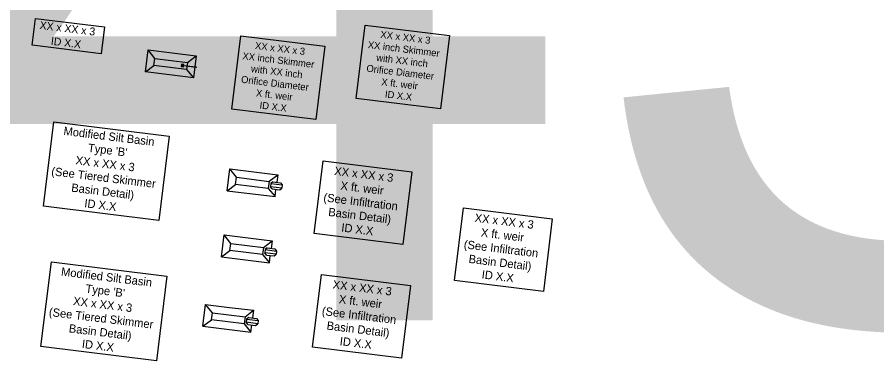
# Model space of a CAD drawing. Extents: x 2470000 to 2520000, y 340000 to 380000.
# Drawn here: x 2482787 to 2483776, y 373398 to 373794 of the extents above; entities that cross this region are included whole.
import ezdxf

# ---------------------------------------------------------------- set-up
doc = ezdxf.new("R2010")
doc.units = 0
for name, color, linetype in [('Infiltration Basin Both CELL', 7, 'Continuous'), ('Infiltration Basin CG CELL', 7, 'Continuous'), ('Infiltration Basin Final CELL', 7, 'Continuous'), ('Infiltration Basin Note Both CELL', 7, 'Continuous'), ('Infiltration Basin Note CG CELL', 7, 'Continuous'), ('Infiltration Basin Note Final CELL', 7, 'Continuous'), ('Modified Silt Basin Type B Note Both CELL', 7, 'Continuous'), ('Modified Silt Basin Type B Note Final CELL', 7, 'Continuous'), ('Scratch_Level_6', 7, 'Continuous'), ('Silt Basin Type B Note Final CELL', 7, 'Continuous'), ('Skimmer Basin Final CELL', 7, 'Continuous'), ('Skimmer Basin Note Both CELL', 7, 'Continuous'), ('Skimmer Basin Note Final CELL', 7, 'Continuous')]:
    doc.layers.add(name, color=color, linetype=linetype)

msp = doc.modelspace()

# ---------------------------------------------------------------- linework, layer by layer
at = {"layer": 'Infiltration Basin Both CELL'}
for p, q in [((2483021.8, 373517.92), (2483024.91, 373543.09)), ((2483032.65, 373533.35), (2483024.91, 373543.09)), ((2483024.91, 373543.09), (2483052.49, 373539.7)), ((2483052.49, 373539.7), (2483080.06, 373536.29)), ((2483031.66, 373525.19), (2483032.65, 373533.35)), ((2483032.65, 373533.35), (2483070.21, 373528.67)), ((2483070.23, 373528.73), (2483080.06, 373536.29)), ((2483080.06, 373536.29), (2483079, 373527.59)), ((2483021.8, 373517.92), (2483031.68, 373525.16)), ((2483069.21, 373520.54), (2483031.66, 373525.19)), ((2483070.21, 373528.67), (2483069.21, 373520.54)), ((2483069.21, 373520.54), (2483076.99, 373511.14)), ((2483072.07, 373526.15), (2483071.63, 373522.49)), ((2483073.59, 373519.98), (2483071.63, 373522.49)), ((2483084.92, 373520.87), (2483071.63, 373522.49)), ((2483074.58, 373528.12), (2483072.07, 373526.15)), ((2483072.07, 373526.15), (2483085.37, 373524.55)), ((2483073.59, 373519.98), (2483082.41, 373518.91)), ((2483074.58, 373528.12), (2483083.42, 373527.05)), ((2483082.41, 373518.91), (2483084.92, 373520.87)), ((2483083.42, 373527.05), (2483085.37, 373524.55)), ((2483085.37, 373524.55), (2483084.92, 373520.87)), ((2483021.8, 373517.92), (2483076.99, 373511.14)), ((2483076.99, 373511.14), (2483078.01, 373519.46))]:
    msp.add_line(p, q, dxfattribs=at)
at = {"layer": 'Infiltration Basin CG CELL'}
for p, q in [((2483028.31, 373594.06), (2483031.42, 373619.22)), ((2483039.16, 373609.49), (2483031.42, 373619.22)), ((2483031.42, 373619.22), (2483059, 373615.83)), ((2483038.17, 373601.33), (2483039.16, 373609.49)), ((2483039.16, 373609.49), (2483076.72, 373604.8)), ((2483059, 373615.83), (2483086.57, 373612.43)), ((2483076.74, 373604.87), (2483086.57, 373612.43)), ((2483086.57, 373612.43), (2483085.51, 373603.72)), ((2483028.31, 373594.06), (2483038.18, 373601.29)), ((2483075.72, 373596.68), (2483038.17, 373601.33)), ((2483076.72, 373604.8), (2483075.72, 373596.68)), ((2483078.58, 373602.29), (2483078.14, 373598.62)), ((2483081.09, 373604.25), (2483078.58, 373602.29)), ((2483078.58, 373602.29), (2483091.88, 373600.69)), ((2483081.09, 373604.25), (2483089.92, 373603.19)), ((2483089.92, 373603.19), (2483091.88, 373600.69)), ((2483091.88, 373600.69), (2483091.43, 373597.01)), ((2483028.31, 373594.06), (2483083.5, 373587.27)), ((2483075.72, 373596.68), (2483083.5, 373587.27)), ((2483080.1, 373596.12), (2483078.14, 373598.62)), ((2483091.43, 373597.01), (2483078.14, 373598.62)), ((2483080.1, 373596.12), (2483088.92, 373595.05)), ((2483083.5, 373587.27), (2483084.52, 373595.6)), ((2483088.92, 373595.05), (2483091.43, 373597.01))]:
    msp.add_line(p, q, dxfattribs=at)
at = {"layer": 'Infiltration Basin Final CELL'}
for p, q in [((2483000.57, 373437.9), (2483003.68, 373463.06)), ((2483011.41, 373453.33), (2483003.68, 373463.06)), ((2483003.68, 373463.06), (2483031.25, 373459.67)), ((2483010.43, 373445.17), (2483011.41, 373453.33)), ((2483011.41, 373453.33), (2483048.97, 373448.64)), ((2483031.25, 373459.67), (2483058.83, 373456.26)), ((2483049, 373448.71), (2483058.83, 373456.26)), ((2483058.83, 373456.26), (2483057.76, 373447.56)), ((2483000.57, 373437.9), (2483010.44, 373445.13)), ((2483047.97, 373440.52), (2483010.43, 373445.17)), ((2483048.97, 373448.64), (2483047.97, 373440.52)), ((2483050.83, 373446.13), (2483050.4, 373442.46)), ((2483052.35, 373439.96), (2483050.4, 373442.46)), ((2483063.68, 373440.84), (2483050.4, 373442.46)), ((2483053.35, 373448.09), (2483050.83, 373446.13)), ((2483050.83, 373446.13), (2483064.13, 373444.53)), ((2483053.35, 373448.09), (2483062.18, 373447.03)), ((2483061.17, 373438.88), (2483063.68, 373440.84)), ((2483062.18, 373447.03), (2483064.13, 373444.53)), ((2483064.13, 373444.53), (2483063.68, 373440.84)), ((2483000.57, 373437.9), (2483055.75, 373431.11)), ((2483047.97, 373440.52), (2483055.75, 373431.11)), ((2483052.35, 373439.96), (2483061.17, 373438.88)), ((2483055.75, 373431.11), (2483056.78, 373439.43))]:
    msp.add_line(p, q, dxfattribs=at)
at = {"layer": 'Infiltration Basin Note Both CELL'}
msp.add_lwpolyline([(2483137.07, 373497.55), (2483239.16, 373485), (2483228.86, 373401.19), (2483126.77, 373413.74)], close=True, dxfattribs=at)
at = {"layer": 'Infiltration Basin Note CG CELL'}
msp.add_lwpolyline([(2483138.91, 373628.4), (2483240.99, 373615.85), (2483230.69, 373532.04), (2483128.61, 373544.59)], close=True, dxfattribs=at)
at = {"layer": 'Infiltration Basin Note Final CELL'}
msp.add_lwpolyline([(2483300.39, 373574.36), (2483402.47, 373561.81), (2483392.17, 373478), (2483290.09, 373490.55)], close=True, dxfattribs=at)
at = {"layer": 'Modified Silt Basin Type B Note Both CELL'}
msp.add_lwpolyline([(2482829, 373673.38), (2482961.91, 373657.04), (2482949.96, 373559.84), (2482817.05, 373576.18)], close=True, dxfattribs=at)
at = {"layer": 'Modified Silt Basin Type B Note Final CELL'}
msp.add_lwpolyline([(2482826.25, 373511.93), (2482959.16, 373495.59), (2482947.17, 373398.08), (2482814.26, 373414.42)], close=True, dxfattribs=at)
at = {"layer": 'Silt Basin Type B Note Final CELL'}
msp.add_lwpolyline([(2482807.82, 373792.46), (2482887.42, 373782.68), (2482883.64, 373751.88), (2482804.04, 373761.66)], close=True, dxfattribs=at)
at = {"layer": 'Skimmer Basin Final CELL'}
for p, q in [((2482934.37, 373730.98), (2482937.48, 373756.15)), ((2482945.21, 373746.41), (2482937.48, 373756.15)), ((2482937.48, 373756.15), (2482965.05, 373752.76)), ((2482965.05, 373752.76), (2482992.63, 373749.35)), ((2482982.8, 373741.79), (2482992.63, 373749.35)), ((2482992.63, 373749.35), (2482989.55, 373724.2)), ((2482934.37, 373730.98), (2482944.24, 373738.22)), ((2482944.23, 373738.25), (2482945.21, 373746.41)), ((2482981.77, 373733.61), (2482944.23, 373738.25)), ((2482945.21, 373746.41), (2482982.77, 373741.73)), ((2482975.84, 373739.91), (2482975.49, 373737.07)), ((2482978.49, 373739.58), (2482975.84, 373739.91)), ((2482976.25, 373739.39), (2482976.02, 373737.47)), ((2482976.02, 373737.47), (2482977.73, 373737.26)), ((2482977.96, 373739.17), (2482976.25, 373739.39)), ((2482977.73, 373737.26), (2482977.96, 373739.17)), ((2482978.14, 373736.74), (2482978.49, 373739.58)), ((2482992.86, 373736.12), (2482978.28, 373737.93)), ((2482978.34, 373738.39), (2482992.92, 373736.58)), ((2482982.77, 373741.73), (2482981.77, 373733.61)), ((2482961.99, 373727.59), (2482934.37, 373730.98)), ((2482989.58, 373724.18), (2482961.99, 373727.59)), ((2482975.49, 373737.07), (2482978.14, 373736.74)), ((2482981.77, 373733.61), (2482989.55, 373724.2)), ((2482992.92, 373736.58), (2482992.86, 373736.12))]:
    msp.add_line(p, q, dxfattribs=at)
at = {"layer": 'Skimmer Basin Note Both CELL'}
msp.add_lwpolyline([(2483044.17, 373772.45), (2483140.71, 373760.58), (2483130.34, 373676.24), (2483033.81, 373688.11)], close=True, dxfattribs=at)
at = {"layer": 'Skimmer Basin Note Final CELL'}
msp.add_lwpolyline([(2483187.1, 373784.73), (2483284.31, 373772.78), (2483273.94, 373688.44), (2483176.74, 373700.39)], close=True, dxfattribs=at)

# ---------------------------------------------------------------- texts
at = {"layer": 'Infiltration Basin Note Both CELL'}
for s, height, p in [('XX x XX x 3', 9.5659, (2483149.43, 373481.53)), ('X ft. weir', 9.566, (2483156.56, 373464.59)), ('(See Infiltration', 9.5659, (2483136.96, 373450.94)), ('Basin Detail)', 9.5659, (2483142.49, 373434.19)), ('ID X.X', 9.566, (2483157.52, 373416.28))]:
    msp.add_text(s, height=height, rotation=352.99213, dxfattribs=at).set_placement(p)
at = {"layer": 'Infiltration Basin Note CG CELL'}
for s, height, p in [('XX x XX x 3', 9.5659, (2483151.26, 373612.38)), ('X ft. weir', 9.566, (2483158.4, 373595.44)), ('(See Infiltration', 9.5659, (2483138.8, 373581.79)), ('Basin Detail)', 9.5659, (2483144.33, 373565.04)), ('ID X.X', 9.566, (2483159.36, 373547.13))]:
    msp.add_text(s, height=height, rotation=352.99213, dxfattribs=at).set_placement(p)
at = {"layer": 'Infiltration Basin Note Final CELL'}
for s, height, p in [('XX x XX x 3', 9.5659, (2483312.74, 373558.34)), ('X ft. weir', 9.566, (2483319.88, 373541.4)), ('(See Infiltration', 9.5659, (2483300.27, 373527.74)), ('Basin Detail)', 9.5659, (2483305.81, 373511)), ('ID X.X', 9.566, (2483320.84, 373493.09))]:
    msp.add_text(s, height=height, rotation=352.99213, dxfattribs=at).set_placement(p)
at = {"layer": 'Modified Silt Basin Type B Note Both CELL'}
for s, height, p in [('Modified Silt Basin', 9.5659, (2482839.82, 373658.4)), ("Type 'B'", 9.566, (2482867.9, 373638.88)), ('XX x XX x 3', 9.5659, (2482853.7, 373624.56)), ('(See Tiered Skimmer', 9.5659, (2482825.78, 373611.93)), ('Basin Detail)', 9.5659, (2482848.71, 373593.05)), ('ID X.X', 9.566, (2482863.74, 373575.14))]:
    msp.add_text(s, height=height, rotation=352.99213, dxfattribs=at).set_placement(p)
at = {"layer": 'Modified Silt Basin Type B Note Final CELL'}
for s, height, p in [('Modified Silt Basin', 9.5659, (2482836.99, 373496.32)), ("Type 'B'", 9.566, (2482865.07, 373476.81)), ('XX x XX x 3', 9.5659, (2482850.88, 373462.49)), ('(See Tiered Skimmer', 9.5659, (2482822.96, 373449.86)), ('Basin Detail)', 9.5659, (2482845.89, 373430.98)), ('ID X.X', 9.566, (2482860.91, 373413.07))]:
    msp.add_text(s, height=height, rotation=352.99213, dxfattribs=at).set_placement(p)
at = {"layer": 'Scratch_Level_6'}
msp.add_text('4387', height=1000, dxfattribs=at).set_placement((2482689.75, 373444.66))
at = {"layer": 'Silt Basin Type B Note Final CELL'}
for s, p in [('XX x XX x 3', (2482812.34, 373780.46)), ('ID X.X', (2482825.26, 373762.25))]:
    msp.add_text(s, height=9, rotation=352.99213, dxfattribs=at).set_placement(p)
at = {"layer": 'Skimmer Basin Note Both CELL'}
for s, p in [('XX x XX x 3', (2483060.15, 373757.38)), ('XX inch Skimmer', (2483045.65, 373745.56)), ('with XX inch', (2483055.47, 373730.75)), ('Orifice Diameter', (2483044.08, 373718.55)), ('X ft. weir', (2483061.25, 373702.83)), ('ID X.X', (2483065.35, 373688.73))]:
    msp.add_text(s, height=8.1, rotation=352.99213, dxfattribs=at).set_placement(p)
at = {"layer": 'Skimmer Basin Note Final CELL'}
for s, p in [('XX x XX x 3', (2483204.35, 373770.16)), ('XX inch Skimmer', (2483189.85, 373758.34)), ('with XX inch', (2483199.67, 373743.53)), ('Orifice Diameter', (2483188.27, 373731.33)), ('X ft. weir', (2483205.45, 373715.62)), ('ID X.X', (2483209.55, 373701.51))]:
    msp.add_text(s, height=8.1, rotation=352.99213, dxfattribs=at).set_placement(p)

doc.saveas('drawing.dxf')
